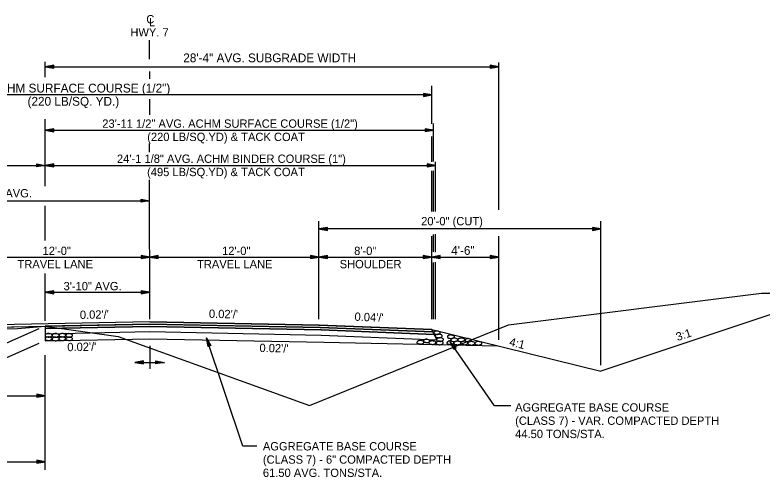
# Model space of a CAD drawing. Extents: x 1398183 to 1398373, y 1967240 to 1968889.
# Drawn here: x 1398252.8 to 1398305.8, y 1967720.5 to 1967753.3 of the extents above; entities that cross this region are included whole.
import ezdxf

# ---------------------------------------------------------------- set-up
doc = ezdxf.new("R2010")
doc.units = 0
for name, color, linetype in [('1', 7, 'Continuous'), ('10', 7, 'Continuous'), ('19', 7, 'Continuous'), ('42', 7, 'Continuous'), ('7', 7, 'Continuous'), ('Level 1', 7, 'Continuous')]:
    doc.layers.add(name, color=color, linetype=linetype)

# ---------------------------------------------------------------- blocks, each defined once
blk = doc.blocks.new('ROCKS')
at = {"layer": '1'}
blk.add_spline([(0.013, 0.06), (0.053, 0.053), (0.107, 0.033), (0.133, 0.013), (0.133, -0.007), (0.12, -0.033), (0.107, -0.04), (0.073, -0.053), (0.033, -0.067), (0.013, -0.067), (-0.02, -0.06), (-0.06, -0.053), (-0.087, -0.047), (-0.113, -0.02), (-0.113, -0.007), (-0.107, 0.02), (-0.087, 0.033), (-0.067, 0.047), (-0.033, 0.053), (-0.02, 0.06), (0.013, 0.06)], degree=3, dxfattribs=at)

msp = doc.modelspace()

# ---------------------------------------------------------------- linework, layer by layer
at = {"layer": '19'}
for p, q in [((1398255.569, 1967749.744), (1398254.969, 1967749.639)), ((1398254.969, 1967749.639), (1398287.124, 1967749.639)), ((1398254.969, 1967749.639), (1398255.569, 1967749.534)), ((1398255.569, 1967749.689), (1398255.129, 1967749.654)), ((1398255.129, 1967749.624), (1398255.569, 1967749.584)), ((1398255.569, 1967749.534), (1398255.569, 1967749.744)), ((1398286.524, 1967749.744), (1398286.524, 1967749.534)), ((1398287.124, 1967749.639), (1398286.524, 1967749.744)), ((1398286.964, 1967749.654), (1398286.524, 1967749.689)), ((1398286.524, 1967749.534), (1398287.124, 1967749.639)), ((1398286.524, 1967749.584), (1398286.964, 1967749.624)), ((1398282.379, 1967745.593), (1398282.379, 1967748.287)), ((1398282.379, 1967747.639), (1398232.379, 1967747.639)), ((1398281.779, 1967747.744), (1398281.779, 1967747.534)), ((1398282.379, 1967747.639), (1398281.779, 1967747.744)), ((1398282.219, 1967747.654), (1398281.779, 1967747.689)), ((1398281.779, 1967747.534), (1398282.379, 1967747.639)), ((1398281.779, 1967747.584), (1398282.219, 1967747.624)), ((1398282.502, 1967742.907), (1398282.502, 1967745.622)), ((1398255.569, 1967745.244), (1398254.969, 1967745.139)), ((1398254.969, 1967745.139), (1398282.502, 1967745.139)), ((1398254.969, 1967745.139), (1398255.569, 1967745.034)), ((1398255.569, 1967745.189), (1398255.129, 1967745.154)), ((1398255.129, 1967745.124), (1398255.569, 1967745.084)), ((1398255.569, 1967745.034), (1398255.569, 1967745.244)), ((1398281.902, 1967745.245), (1398281.902, 1967745.035)), ((1398282.502, 1967745.14), (1398281.902, 1967745.245)), ((1398282.342, 1967745.155), (1398281.902, 1967745.19)), ((1398281.902, 1967745.035), (1398282.502, 1967745.14)), ((1398281.902, 1967745.085), (1398282.342, 1967745.125)), ((1398282.379, 1967742.887), (1398282.379, 1967744.683)), ((1398254.369, 1967742.534), (1398254.369, 1967742.744)), ((1398254.369, 1967742.744), (1398254.969, 1967742.639)), ((1398254.369, 1967742.689), (1398254.809, 1967742.654)), ((1398255.569, 1967742.744), (1398254.969, 1967742.639)), ((1398255.569, 1967742.689), (1398255.129, 1967742.654)), ((1398255.569, 1967742.534), (1398255.569, 1967742.744)), ((1398282.039, 1967742.745), (1398282.039, 1967742.535)), ((1398282.639, 1967742.64), (1398282.039, 1967742.745)), ((1398282.479, 1967742.655), (1398282.039, 1967742.69)), ((1398282.639, 1967739.382), (1398282.639, 1967742.905)), ((1398232.385, 1967742.639), (1398282.639, 1967742.639)), ((1398254.969, 1967742.639), (1398254.369, 1967742.534)), ((1398254.809, 1967742.624), (1398254.369, 1967742.584)), ((1398254.969, 1967742.639), (1398255.569, 1967742.534)), ((1398255.129, 1967742.624), (1398255.569, 1967742.584)), ((1398282.039, 1967742.535), (1398282.639, 1967742.64)), ((1398282.039, 1967742.585), (1398282.479, 1967742.625)), ((1398282.379, 1967739.382), (1398282.379, 1967742.263)), ((1398282.501, 1967739.382), (1398282.502, 1967742.263)), ((1398242.966, 1967740.139), (1398262.373, 1967740.139)), ((1398261.773, 1967740.034), (1398261.773, 1967740.244)), ((1398261.773, 1967740.244), (1398262.373, 1967740.139)), ((1398261.773, 1967740.189), (1398262.213, 1967740.154)), ((1398262.373, 1967740.139), (1398261.773, 1967740.034)), ((1398262.213, 1967740.124), (1398261.773, 1967740.084)), ((1398274.374, 1967731.738), (1398274.373, 1967738.686)), ((1398274.974, 1967738.244), (1398274.374, 1967738.139)), ((1398294.374, 1967738.139), (1398274.374, 1967738.139)), ((1398274.374, 1967738.139), (1398274.974, 1967738.034)), ((1398274.974, 1967738.189), (1398274.534, 1967738.154)), ((1398274.534, 1967738.124), (1398274.974, 1967738.084)), ((1398274.974, 1967738.034), (1398274.974, 1967738.244)), ((1398293.774, 1967738.244), (1398293.774, 1967738.034)), ((1398294.374, 1967738.139), (1398293.774, 1967738.244)), ((1398294.214, 1967738.154), (1398293.774, 1967738.189)), ((1398293.774, 1967738.034), (1398294.374, 1967738.139)), ((1398293.774, 1967738.084), (1398294.214, 1967738.124)), ((1398282.374, 1967731.739), (1398282.373, 1967737.626)), ((1398282.502, 1967736.501), (1398282.501, 1967737.748)), ((1398282.639, 1967736.496), (1398282.639, 1967737.752)), ((1398248.374, 1967736.139), (1398260.374, 1967736.139)), ((1398260.374, 1967736.139), (1398282.374, 1967736.139)), ((1398261.774, 1967736.244), (1398261.774, 1967736.034)), ((1398262.374, 1967736.139), (1398261.774, 1967736.244)), ((1398262.214, 1967736.154), (1398261.774, 1967736.189)), ((1398261.774, 1967736.034), (1398262.374, 1967736.139)), ((1398261.774, 1967736.084), (1398262.214, 1967736.124)), ((1398262.974, 1967736.244), (1398262.374, 1967736.139)), ((1398262.374, 1967736.139), (1398262.974, 1967736.034)), ((1398262.974, 1967736.189), (1398262.534, 1967736.154)), ((1398262.534, 1967736.124), (1398262.974, 1967736.084)), ((1398262.974, 1967736.034), (1398262.974, 1967736.244)), ((1398273.774, 1967736.244), (1398273.774, 1967736.034)), ((1398274.374, 1967736.139), (1398273.774, 1967736.244)), ((1398274.214, 1967736.154), (1398273.774, 1967736.189)), ((1398273.774, 1967736.034), (1398274.374, 1967736.139)), ((1398273.774, 1967736.084), (1398274.214, 1967736.124)), ((1398274.974, 1967736.244), (1398274.374, 1967736.139)), ((1398274.374, 1967736.139), (1398274.974, 1967736.034)), ((1398274.974, 1967736.189), (1398274.534, 1967736.154)), ((1398274.534, 1967736.124), (1398274.974, 1967736.084)), ((1398274.974, 1967736.034), (1398274.974, 1967736.244)), ((1398281.774, 1967736.244), (1398281.774, 1967736.034)), ((1398282.374, 1967736.139), (1398281.774, 1967736.244)), ((1398282.214, 1967736.154), (1398281.774, 1967736.189)), ((1398281.774, 1967736.034), (1398282.374, 1967736.139)), ((1398281.774, 1967736.084), (1398282.214, 1967736.124)), ((1398282.974, 1967736.244), (1398282.374, 1967736.139)), ((1398282.374, 1967736.139), (1398287.12, 1967736.139)), ((1398282.374, 1967736.139), (1398282.974, 1967736.034)), ((1398282.974, 1967736.189), (1398282.534, 1967736.154)), ((1398282.534, 1967736.124), (1398282.974, 1967736.084)), ((1398282.639, 1967731.739), (1398282.639, 1967735.768)), ((1398282.974, 1967736.034), (1398282.974, 1967736.244)), ((1398286.521, 1967736.244), (1398286.521, 1967736.034)), ((1398287.121, 1967736.139), (1398286.521, 1967736.244)), ((1398286.961, 1967736.154), (1398286.521, 1967736.189)), ((1398286.521, 1967736.034), (1398287.121, 1967736.139)), ((1398286.521, 1967736.084), (1398286.961, 1967736.124)), ((1398282.501, 1967731.739), (1398282.501, 1967735.759)), ((1398255.568, 1967733.744), (1398254.968, 1967733.639)), ((1398255.568, 1967733.689), (1398255.128, 1967733.654)), ((1398255.568, 1967733.534), (1398255.568, 1967733.744)), ((1398261.774, 1967733.744), (1398261.774, 1967733.534)), ((1398262.374, 1967733.639), (1398261.774, 1967733.744)), ((1398262.214, 1967733.654), (1398261.774, 1967733.689)), ((1398254.968, 1967733.639), (1398262.374, 1967733.639)), ((1398254.968, 1967733.639), (1398255.568, 1967733.534)), ((1398255.128, 1967733.624), (1398255.568, 1967733.584)), ((1398261.774, 1967733.534), (1398262.374, 1967733.639)), ((1398261.774, 1967733.584), (1398262.214, 1967733.624)), ((1398310.965, 1967733.585), (1398294.374, 1967728.054)), ((1398262.374, 1967731.556), (1398238.374, 1967731.076)), ((1398262.374, 1967731.556), (1398274.374, 1967731.316)), ((1398254.509, 1967731.04), (1398252.213, 1967730.029)), ((1398254.966, 1967731.241), (1398254.966, 1967731.074)), ((1398254.966, 1967731.074), (1398254.966, 1967730.699)), ((1398274.542, 1967730.976), (1398262.374, 1967731.223)), ((1398274.374, 1967731.316), (1398282.374, 1967730.996)), ((1398282.374, 1967730.996), (1398294.374, 1967728.054)), ((1398282.374, 1967730.996), (1398282.459, 1967730.826)), ((1398254.966, 1967730.699), (1398254.966, 1967730.199)), ((1398274.538, 1967730.601), (1398282.735, 1967730.273)), ((1398282.544, 1967730.656), (1398274.542, 1967730.976)), ((1398282.459, 1967730.826), (1398282.544, 1967730.656)), ((1398282.544, 1967730.656), (1398282.735, 1967730.273)), ((1398282.735, 1967730.273), (1398282.544, 1967730.656)), ((1398254.507, 1967729.998), (1398252.213, 1967728.986)), ((1398268.968, 1967722.734), (1398266.414, 1967730.401)), ((1398266.516, 1967729.802), (1398266.414, 1967730.401)), ((1398266.414, 1967730.401), (1398266.713, 1967729.87)), ((1398266.562, 1967729.819), (1398266.452, 1967730.245)), ((1398266.479, 1967730.255), (1398266.662, 1967729.855)), ((1398286.826, 1967725.579), (1398283.68, 1967730.131)), ((1398283.933, 1967729.579), (1398283.68, 1967730.131)), ((1398283.68, 1967730.131), (1398284.106, 1967729.695)), ((1398283.974, 1967729.607), (1398283.757, 1967729.99)), ((1398283.78, 1967730.007), (1398284.061, 1967729.668)), ((1398266.713, 1967729.87), (1398266.516, 1967729.802)), ((1398284.106, 1967729.695), (1398283.933, 1967729.579)), ((1398254.967, 1967721.051), (1398254.966, 1967729.191)), ((1398232.374, 1967726.302), (1398254.967, 1967726.302)), ((1398254.367, 1967726.407), (1398254.367, 1967726.197)), ((1398254.967, 1967726.302), (1398254.367, 1967726.407)), ((1398254.807, 1967726.317), (1398254.367, 1967726.352)), ((1398254.367, 1967726.197), (1398254.967, 1967726.302)), ((1398254.367, 1967726.247), (1398254.807, 1967726.287)), ((1398287.977, 1967725.579), (1398286.826, 1967725.579)), ((1398269.981, 1967722.734), (1398268.968, 1967722.734)), ((1398230.967, 1967721.625), (1398254.967, 1967721.625)), ((1398254.367, 1967721.73), (1398254.367, 1967721.52)), ((1398254.967, 1967721.625), (1398254.367, 1967721.73)), ((1398254.807, 1967721.64), (1398254.367, 1967721.675)), ((1398254.367, 1967721.52), (1398254.967, 1967721.625)), ((1398254.367, 1967721.57), (1398254.807, 1967721.61))]:
    msp.add_line(p, q, dxfattribs=at)
for points in [[(1398260.14, 1967730.516), (1398273.709, 1967725.611), (1398287.825, 1967731.321), (1398305.763, 1967733.585), (1398324.954, 1967733.585)], [(1398232.289, 1967730.666), (1398238.289, 1967730.906), (1398254.966, 1967731.241), (1398262.374, 1967731.389), (1398274.459, 1967731.146), (1398282.459, 1967730.826)], [(1398242.966, 1967730.832), (1398253.001, 1967731.064), (1398254.966, 1967731.241)], [(1398254.966, 1967731.241), (1398260.14, 1967730.516)], [(1398254.966, 1967731.074), (1398262.374, 1967731.223), (1398274.542, 1967730.976)], [(1398262.374, 1967731.223), (1398254.966, 1967731.074), (1398254.966, 1967730.699)], [(1398254.966, 1967730.699), (1398262.374, 1967730.848), (1398274.538, 1967730.601)], [(1398254.966, 1967730.699), (1398262.374, 1967730.848), (1398274.538, 1967730.601)], [(1398274.538, 1967730.601), (1398282.735, 1967730.273)], [(1398274.542, 1967730.976), (1398282.544, 1967730.656)], [(1398254.966, 1967730.199), (1398262.374, 1967730.348), (1398274.733, 1967730.097), (1398287.06, 1967729.847)]]:
    msp.add_lwpolyline(points, dxfattribs=at)
for points in [[(1398232.289, 1967730.666), (1398238.289, 1967730.906), (1398262.374, 1967731.389), (1398274.459, 1967731.146), (1398282.459, 1967730.826), (1398282.374, 1967730.996), (1398274.386, 1967731.314), (1398262.374, 1967731.556), (1398238.374, 1967731.076), (1398232.374, 1967730.836)], [(1398254.966, 1967731.241), (1398254.966, 1967731.074), (1398262.374, 1967731.223), (1398265.306, 1967731.163), (1398274.542, 1967730.976), (1398282.544, 1967730.656), (1398282.459, 1967730.826), (1398274.459, 1967731.146), (1398265.909, 1967731.318), (1398262.374, 1967731.389)]]:
    msp.add_lwpolyline(points, close=True, dxfattribs=at)
at = {"layer": '42'}
for p, q in [((1398262.374, 1967729.85), (1398262.374, 1967728.218)), ((1398261.926, 1967728.774), (1398261.326, 1967728.669)), ((1398261.326, 1967728.669), (1398261.926, 1967728.564)), ((1398261.326, 1967728.669), (1398263.421, 1967728.669)), ((1398261.926, 1967728.719), (1398261.486, 1967728.684)), ((1398261.486, 1967728.654), (1398261.926, 1967728.614)), ((1398261.926, 1967728.564), (1398261.926, 1967728.774)), ((1398262.821, 1967728.564), (1398262.821, 1967728.774)), ((1398262.821, 1967728.774), (1398263.421, 1967728.669)), ((1398262.821, 1967728.719), (1398263.261, 1967728.684)), ((1398263.421, 1967728.669), (1398262.821, 1967728.564)), ((1398263.261, 1967728.654), (1398262.821, 1967728.614))]:
    msp.add_line(p, q, dxfattribs=at)
at = {"layer": '7'}
for p, q in [((1398262.371, 1967750.183), (1398262.371, 1967751.521)), ((1398254.969, 1967748.889), (1398254.969, 1967749.991)), ((1398287.124, 1967739.485), (1398287.123, 1967749.934)), ((1398262.375, 1967748.778), (1398262.375, 1967749.308)), ((1398262.384, 1967746.239), (1398262.384, 1967747.341)), ((1398254.969, 1967741.157), (1398254.969, 1967745.919)), ((1398262.373, 1967743.585), (1398262.373, 1967744.201)), ((1398262.374, 1967731.738), (1398262.373, 1967741.608)), ((1398254.968, 1967737.307), (1398254.968, 1967739.762)), ((1398294.374, 1967728.478), (1398294.373, 1967738.684)), ((1398287.121, 1967730.273), (1398287.12, 1967737.626)), ((1398254.968, 1967731.609), (1398254.968, 1967734.971))]:
    msp.add_line(p, q, dxfattribs=at)

# ---------------------------------------------------------------- block references
at = {"layer": 'Level 1'}
for p, xscale, yscale, rotation in [((1398255.183, 1967730.351), 2.011654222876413, 2.0116542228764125, -0.17361855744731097), ((1398255.191, 1967730.593), 2.011654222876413, 2.0116542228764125, -0.17361855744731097), ((1398255.69, 1967730.591), 2.011654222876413, 2.0116542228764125, -0.17361855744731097), ((1398256.155, 1967730.352), 1.9974694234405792, 1.9974694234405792, -0.17361855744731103), ((1398256.165, 1967730.599), 1.907051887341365, 1.9070518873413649, -0.173618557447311), ((1398256.641, 1967730.587), 1.9598639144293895, 1.959863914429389, -0.173618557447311), ((1398256.652, 1967730.343), 1.890205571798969, 1.8902055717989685, -0.17361855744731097), ((1398282.729, 1967730.779), 1.8771740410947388, 1.8771740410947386, -0.173618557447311), ((1398282.85, 1967730.548), 2.011654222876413, 2.0116542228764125, -0.17361855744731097), ((1398283.715, 1967730.493), 2.011654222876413, 2.0116542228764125, -0.17361855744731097), ((1398255.687, 1967730.333), 2.011654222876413, 2.0116542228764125, -0.17361855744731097), ((1398281.553, 1967730.101), 2.011654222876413, 2.0116542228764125, -0.17361855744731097), ((1398282.001, 1967730.195), 1.8429465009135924, 1.8429465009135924, -0.17361855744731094), ((1398282.399, 1967730.073), 2.011654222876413, 2.0116542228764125, -0.17361855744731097), ((1398282.911, 1967730.053), 2.011654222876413, 2.0116542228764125, -0.17361855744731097), ((1398282.932, 1967730.292), 2.011654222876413, 2.0116542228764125, -0.17361855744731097), ((1398283.681, 1967730.068), 2.011654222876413, 2.0116542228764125, -0.17361855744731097), ((1398283.681, 1967730.068), 2.011654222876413, 2.0116542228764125, -0.17361855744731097), ((1398283.947, 1967730.273), 2.011654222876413, 2.0116542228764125, -0.17361855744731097), ((1398284.173, 1967730.05), 2.011654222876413, 2.0116542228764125, -0.17361855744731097), ((1398284.442, 1967730.273), 2.011654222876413, 2.0116542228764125, -0.17361855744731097), ((1398284.663, 1967730.05), 2.011654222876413, 2.0116542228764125, -0.17361855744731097), ((1398284.663, 1967730.05), 2.011654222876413, 2.0116542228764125, -0.17361855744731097), ((1398284.946, 1967730.248), 1.7335100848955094, 1.7335100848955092, -0.173618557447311), ((1398285.156, 1967730.03), 2.011654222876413, 2.0116542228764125, -0.17361855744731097), ((1398285.156, 1967730.03), 2.011654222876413, 2.0116542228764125, -0.17361855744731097), ((1398285.658, 1967730.03), 2.011654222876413, 2.0116542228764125, -0.17361855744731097), ((1398285.658, 1967730.03), 2.011654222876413, 2.0116542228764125, -0.17361855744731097)]:
    msp.add_blockref('ROCKS', p, dxfattribs=dict(at, xscale=xscale, yscale=yscale, rotation=rotation))

# ---------------------------------------------------------------- texts
at = {"layer": '10'}
for s, height, rotation, p in [('20\'-0" (CUT)', 0.59001, 0, (1398281.623, 1967738.391)), ('12\'-0"', 0.59, 0, (1398254.778, 1967736.285)), ('12\'-0"', 0.59, 0, (1398267.507, 1967736.285)), ('8\'-0" ', 0.59, 0, (1398276.872, 1967736.285)), ('TRAVEL LANE', 0.59001, 0, (1398253.005, 1967735.345)), ('TRAVEL LANE', 0.59001, 0, (1398265.734, 1967735.345)), ('SHOULDER', 0.59, 0, (1398275.845, 1967735.345)), ('3:1', 0.59, 18.4776, (1398299.807, 1967730.176)), ('4:1', 0.59, 346.2636, (1398287.831, 1967729.864))]:
    msp.add_text(s, height=height, rotation=rotation, dxfattribs=at).set_placement(p)
msp.add_text('3\'-10" AVG.', height=0.59001, dxfattribs=at).set_placement((1398256.269, 1967733.784))
at = {"layer": '19'}
for s, height, p in [('C', 0.59, (1398262.138, 1967752.716)), ('L', 0.59, (1398262.327, 1967752.505)), ('HWY. 7', 0.59, (1398261.007, 1967751.786)), ('28\'-4" AVG. SUBGRADE WIDTH', 0.625, (1398264.755, 1967749.957)), ('50\'-0" ACHM SURFACE COURSE (1/2")', 0.625, (1398248.733, 1967747.811)), ('(220 LB/SQ. YD.)', 0.625, (1398253.713, 1967746.874)), ('4\'-6"', 0.625, (1398283.751, 1967736.297))]:
    msp.add_text(s, height=height, dxfattribs=at).set_placement(p)
for s, height, rotation, p in [('16\'-0" AVG.', 0.59001, 0, (1398249.911, 1967740.374)), ("0.02'/'", 0.59, 1.1458, (1398257.429, 1967731.747)), ("0.02'/'", 0.59, 358.8542, (1398266.572, 1967731.828)), ("0.04'/'", 0.59, 357.7094, (1398276.888, 1967731.624)), ("0.02'/'", 0.59, 1.1458, (1398256.54, 1967729.458)), ("0.02'/'", 0.59, 358.8542, (1398270.154, 1967729.406)), ('AGGREGATE BASE COURSE', 0.59001, 360, (1398288.287, 1967725.178)), ('(CLASS 7) - VAR. COMPACTED DEPTH', 0.59001, 360, (1398288.287, 1967724.238)), ('44.50 TONS/STA.', 0.59001, 360, (1398288.287, 1967723.298)), ('AGGREGATE BASE COURSE', 0.59001, 360, (1398270.4, 1967722.422)), ('(CLASS 7) - 6" COMPACTED DEPTH', 0.59001, 360, (1398270.4, 1967721.482)), ('61.50 AVG. TONS/STA.', 0.59001, 360, (1398270.4, 1967720.542))]:
    msp.add_text(s, height=height, rotation=rotation, dxfattribs=at).set_placement(p)
at = {"layer": '42'}
for s, p in [('23\'-11 1/2" AVG. ACHM SURFACE COURSE (1/2")', (1398259.014, 1967745.311)), ('(220 LB/SQ.YD) & TACK COAT', (1398262.198, 1967744.371)), ('24\'-1 1/8" AVG. ACHM BINDER COURSE (1")', (1398260.055, 1967742.82)), ('(495 LB/SQ.YD) & TACK COAT', (1398262.19, 1967741.88))]:
    msp.add_text(s, height=0.59001, rotation=360, dxfattribs=at).set_placement(p)

doc.saveas('drawing.dxf')
